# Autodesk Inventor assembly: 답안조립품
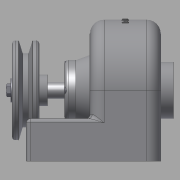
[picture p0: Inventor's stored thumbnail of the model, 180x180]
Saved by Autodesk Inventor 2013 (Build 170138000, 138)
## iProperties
Created: 2015-02
Part Number: 답안조립품
Document SubType Name: Assembly
Designer: Administrator
Author: Administrator
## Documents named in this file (14)
- C:\Users\Administrator\Desktop\450216V1003\답안조립품.iam
- C:\Users\Administrator\Desktop\450216V1003\본체.ipt
- C:\Users\Administrator\Desktop\450216V1003\축커버.ipt
- C:\Users\Administrator\Desktop\450216V1003\축.ipt
- C:\Users\Administrator\Desktop\450216V1003\베어링 6001.ipt
- C:\Users\Administrator\Desktop\450216V1003\오일실.ipt
- C:\Users\Administrator\Desktop\450216V1003\키4x4.ipt
- C:\Users\Administrator\Desktop\450216V1003\키5x5.ipt
- C:\Users\Administrator\Desktop\450216V1003\스퍼기어.ipt
- C:\Users\Administrator\Desktop\450216V1003\V-벨트풀리.ipt
- C:\Users\Administrator\Desktop\450216V1003\M3x0.5.ipt
- C:\Users\Administrator\Desktop\450216V1003\M5x0.8.ipt
- M5x0.8.ipt
- C:\Users\Administrator\Desktop\450216V1003\와샤.ipt
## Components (6 placed, 3 different names)
1. V-벨트풀리:1 — 각도:3
2. M5x0.8:1 — 각도:5
3. M3x0.5:1
4. M3x0.5:2
5. M3x0.5:3
6. M3x0.5:4
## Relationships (2: Angle 2)
- 각도:3 [Angle]: V-벨트풀리:1
- 각도:5 [Angle]: M5x0.8:1
